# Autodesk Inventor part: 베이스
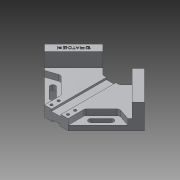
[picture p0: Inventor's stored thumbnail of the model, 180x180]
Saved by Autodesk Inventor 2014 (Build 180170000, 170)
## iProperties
Created: 2019-04
Part Number: 베이스
Material: 알루미늄 6061
Document SubType Name: Modeling
Designer: kb542-22
Density: 2.71 g/cm^3
Appearance: 알루미늄 - 평지
Mass: 603.559 g
Surface Area: 426.17 cm^2
Volume: 222.716 cm^3
Author: kb542-22
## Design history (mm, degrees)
sketch "스케치1"
  geometry: L1 (0, 84.853)-(-35.355, 49.497); L2 (-84.853, 0)-(-20, -64.853); L3 (20, -64.853)-(84.853, 0); L4 (35.355, 49.497)-(0, 84.853); L5 (-20, -64.853)-(20, -64.853) reference; L6 (-20, -64.853)-(0, -84.853); L7 (0, -84.853)-(20, -64.853); L8 (-14.005, 28.147)-(14.005, 28.147); L9 (14.005, 28.147)-(35.355, 49.497); L10 (35.355, 49.497)-(84.853, 0); L11 (-35.355, 49.497)-(-84.853, 0); L12 (-14.005, 28.147)-(-35.355, 49.497); 2 further points
  constraints: 24 end point, 6 parallel, 4 perpendicular, 2 horizontal, 2 horizontal alignment, 2 vertical alignment, 1 midpoint
  dimensions: "d0" = 120 distance between parallel lines of L3 L1; "d2" = 20 distance from line of L6.end L5; "d4" = 93 distance between parallel lines of L5 L8; "d7" = 50 distance between parallel lines of L4 L12
extrude "돌출1" new body sketch "스케치1" distance "d8" = 18; taper "d9" = 0 deg
sketch "스케치2"
  geometry: L1 (-84.853, 0)-(-20, -64.853) reference; L2 (-20, -64.853)-(20, -64.853) reference; L3 (20, -64.853)-(84.853, 0) reference; L4 (84.853, 0)-(35.355, 49.497) reference; L5 (35.355, 49.497)-(14.005, 28.147) reference; L6 (14.005, 28.147)-(-14.005, 28.147) reference; L7 (-35.355, 49.497)-(-84.853, 0) reference; L8 (-20, -64.853)-(-20, -36.569); L9 (-20, -36.569)-(-49.497, -7.071); L10 (-49.497, -7.071)-(-70.711, -14.142); L11 (0, 28.147)-(0, -64.853); L12 (20, -36.569)-(49.497, -7.071); L13 (49.497, -7.071)-(70.711, -14.142); L14 (20, -64.853)-(20, -36.569); L15 (35.355, 49.497)-(14.005, 28.147) reference; L16 (24.749, 38.891)-(74.246, -10.607); L17 (-24.749, 38.891)-(-74.246, -10.607); L18 (-49.497, -21.213)-(-32.527, -38.184); L19 (-46.315, -18.031)-(-29.345, -35.002); L20 (-35.709, -41.366)-(-52.679, -24.395); L21 (46.315, -18.031)-(29.345, -35.002); L22 (35.709, -41.366)-(52.679, -24.395); L23 (49.497, -21.213)-(32.527, -38.184); L24 (-74.246, -10.607)-(-84.853, 0); L25 (-35.355, 49.497)-(-24.749, 38.891); L26 (-84.853, 0)-(-35.355, 49.497); L27 (-70.711, -14.142)-(-20, -64.853); L28 (20, -64.853)-(70.711, -14.142); L29 (24.749, 38.891)-(35.355, 49.497); L30 (35.355, 49.497)-(84.853, 0); L31 (74.246, -10.607)-(84.853, 0); A1 r 4.5 centre (-49.497, -21.213) between (-46.315, -18.031) and (-52.679, -24.395); A2 r 4.5 centre (-32.527, -38.184) between (-35.709, -41.366) and (-29.345, -35.002); A3 r 4.5 centre (32.527, -38.184) between (29.345, -35.002) and (35.709, -41.366); A4 r 4.5 centre (49.497, -21.213) between (52.679, -24.395) and (46.315, -18.031); 6 further points
  constraints: 50 end point, 13 symmetric about line, 8 point on circle, 6 perpendicular, 5 collinear, 4 centre point, 4 tangent, 3 midpoint, 3 point on line, 2 parallel, 1 vertical alignment, 2 other
  dimensions: "d10" = 20 distance from line of L7 L10.end; "d11" = 20 distance between parallel lines of L1 L9; "d13" = 15 distance between parallel lines of L4 L16; "d14" = 6 distance from line of L2 point (-14, -58.853); "d15" = 12 distance of point (-14, -46.853) point (-14, -58.853); "d16" = 28 distance of point (14, -58.853) point (-14, -58.853); "d17" = 30 distance from line of L7 L9.end; "d18" = 10 distance from line of L1 point (-41.012, -29.698); "d19" = 40 distance from line of L7 L18.start; "d20" = 24 distance of L18.start L18.end; "d21" = 9 distance between parallel lines of L19 L20
extrude "돌출2" cut sketch "스케치2" distance "d22" = 10; taper "d23" = 0 deg
extrude "돌출3" cut sketch "스케치2" stored distance "d24" = 10; taper "d25" = 0 deg
extrude "돌출4" join sketch "스케치2" distance "d26" = 24; taper "d27" = 0 deg
hole "구멍1" sketch "스케치2" diameter "d28" = 4.5; stored, may be unused: countersink angle "d32" = 90 deg, drill point angle "d34" = 118 deg; dims "d29" = 6, "d30" = 4.5, "d31" = 10, "d33" = 8
sketch "스케치3"
  geometry: C1 r 2.25 at (-14, -46.853) reference; C2 r 2.25 at (14, -58.853) reference; C3 r 2.25 at (14, -46.853) reference; C4 r 2.25 at (-14, -58.853) reference; 1 further point
hole "구멍2" sketch "스케치3" at (-14, -58.853), (-14, -46.853), (14, -58.853), (14, -46.853) diameter "d35" = 8; stored, may be unused: countersink angle "d39" = 90 deg, drill point angle "d41" = 0 deg; dims "d36" = 6, "d37" = 4.5, "d38" = 10, "d40" = 10
sketch "스케치4"
  geometry: L1 (0, 0)-(40, 0) reference; L2 (0, 18)-(40, 18) reference; L3 (0, 0)-(0, 8) reference; L4 (12, 18)-(12, 14.5); L5 (12, 14.5)-(28, 14.5); L6 (28, 14.5)-(28, 18); L7 (12, 18)-(28, 18); L8 (34.005, 18)-(5.995, 18) reference; L9 (14, 0)-(14, 3); L10 (14, 3)-(26, 3); L11 (26, 3)-(26, 0); L12 (14, 0)-(26, 0); 5 further points
  constraints: 16 end point, 5 perpendicular, 4 midpoint, 4 point on line, 2 collinear, 2 vertical alignment, 1 parallel
  dimensions: "d42" = 3.5 distance between parallel lines of L2 L5; "d43" = 16 distance between parallel lines of L4 L6; "d44" = 3 distance between parallel lines of L12 L10; "d45" = 12 distance between parallel lines of L11 L9
extrude "돌출5" cut sketch "스케치4" stored distance "d46" = 24; taper "d47" = 0 deg
fillet "모깎기1" dims "d48" = 5
sketch "스케치5"
  geometry: L1 (-24.749, 38.891)-(-35.355, 49.497) reference; L2 (-35.355, 49.497)-(-84.853, 0) reference; L3 (-38.013, 31.988)-(-67.343, 2.658); L4 (-67.343, 2.658)-(-71.589, 6.903); L5 (-71.589, 6.903)-(-42.259, 36.233); L6 (-42.259, 36.233)-(-38.013, 31.988); L7 (-40.136, 34.11)-(-69.466, 4.78); L8 (-52.678, 17.323)-(-56.924, 21.568); 3 further points
  constraints: 5 midpoint, 4 end point, 1 coincident, 2 other
  dimensions: "d49" = 7.5 distance from line of L2 point (-54.801, 19.445); "d50" = 35 distance from line of L1 point (-54.801, 19.445)
feature "엠보싱1" sketch "스케치5" dims "d0" = 120, "d2" = 20, "d4" = 93, "d7" = 50, "d51" = 0.5, "d52" = 0
node "솔리드1"
